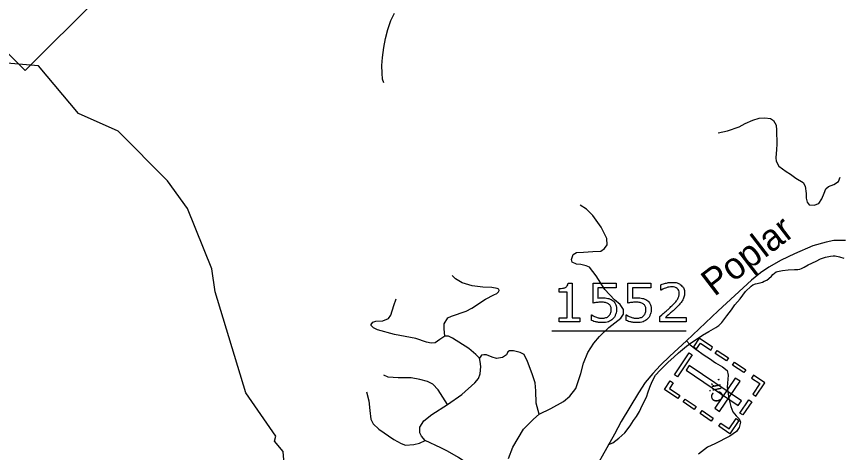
# Model space of a CAD drawing. Extents: x 1190067 to 1192950, y 891516 to 893460.
# Drawn here: x 1190959.3 to 1191052.1, y 893251.8 to 893300.9 of the extents above; entities that cross this region are included whole.
import ezdxf

# ---------------------------------------------------------------- set-up
doc = ezdxf.new("R2010")
doc.units = 0
doc.layers.add('Default', color=7, linetype='Continuous')

msp = doc.modelspace()

# ---------------------------------------------------------------- linework, layer by layer
at = {"layer": 'Default'}
for p, q in [((1190960.312, 893294.828), (1190948.657, 893306.483)), ((1190971.967, 893306.483), (1190960.312, 893294.828)), ((1191019.654, 893265.501), (1191034.784, 893265.501))]:
    msp.add_line(p, q, dxfattribs=at)
for points in [[(1190980.698, 893248.449), (1190979.491, 893247.036), (1190979.736, 893245.425), (1190981.503, 893246.077), (1190983.883, 893247.925), (1190988.976, 893247.078), (1190989.711, 893247.637), (1190989.396, 893251.894), (1190988.398, 893253.063), (1190988.573, 893253.634), (1190985.196, 893258.527), (1190981.713, 893269.914), (1190981.344, 893272.506), (1190978.598, 893279.282), (1190976.358, 893282.428), (1190970.811, 893287.999), (1190966.348, 893289.983), (1190961.814, 893295.359), (1190956.881, 893295.802), (1190952.522, 893297.095), (1190945.977, 893297.974), (1190942.094, 893299.83), (1190938.664, 893302.599), (1190934.899, 893303.824)], [(1190980.698, 893248.449), (1190979.491, 893247.036), (1190979.736, 893245.425), (1190981.503, 893246.077), (1190983.883, 893247.925), (1190988.976, 893247.078), (1190989.711, 893247.637), (1190989.396, 893251.894), (1190988.398, 893253.063), (1190988.573, 893253.634), (1190985.196, 893258.527), (1190981.713, 893269.914), (1190981.344, 893272.506), (1190978.598, 893279.282), (1190976.358, 893282.428), (1190970.811, 893287.999), (1190966.348, 893289.983), (1190961.814, 893295.359), (1190956.881, 893295.802), (1190952.522, 893297.095), (1190945.977, 893297.974), (1190942.094, 893299.83), (1190938.664, 893302.599), (1190934.899, 893303.824)], [(1191000.721, 893293.475), (1191000.59, 893293.864), (1191000.54, 893294.532), (1191000.491, 893295.407), (1191000.588, 893296.317), (1191000.725, 893297.433), (1191000.926, 893298.441), (1191001.198, 893299.45), (1191001.507, 893300.492), (1191001.914, 893301.321)], [(1191038.388, 893287.808), (1191039.447, 893288.049), (1191040.769, 893288.482), (1191041.419, 893288.891), (1191042.285, 893289.252), (1191043.006, 893289.469), (1191043.655, 893289.493), (1191044.281, 893289.445), (1191044.618, 893289.204), (1191044.93, 893288.699), (1191044.978, 893288.121), (1191045.002, 893286.532), (1191044.978, 893285.931), (1191044.882, 893284.992), (1191044.93, 893284.631), (1191045.243, 893284.054), (1191046.061, 893283.476), (1191046.542, 893283.163), (1191047.143, 893282.706), (1191047.985, 893282.224), (1191048.201, 893281.815), (1191048.297, 893280.997), (1191048.321, 893280.467), (1191048.418, 893280.01), (1191048.658, 893279.721), (1191049.211, 893279.673), (1191049.74, 893279.866), (1191050.053, 893280.371), (1191050.342, 893281.021), (1191050.51, 893281.502), (1191050.823, 893281.767), (1191051.424, 893281.984), (1191051.929, 893282.321), (1191052.145, 893282.826)], [(1191014.771, 893251.105), (1191015.276, 893252.381), (1191016.454, 893254.426), (1191017.585, 893255.534), (1191018.21, 893256.111), (1191019.557, 893256.761), (1191020.952, 893257.531), (1191021.673, 893258.133), (1191022.347, 893258.999), (1191022.924, 893260.708), (1191023.236, 893261.863), (1191023.693, 893263.043), (1191024.367, 893264.102), (1191025.04, 893264.872), (1191026.074, 893265.859), (1191027.445, 893266.942), (1191027.734, 893267.375), (1191027.734, 893267.904), (1191027.349, 893268.458), (1191026.724, 893269.011), (1191025.642, 893270.167), (1191024.631, 893271.683), (1191023.91, 893272.67), (1191023.525, 893272.814), (1191022.924, 893272.983), (1191022.419, 893273.007), (1191021.938, 893273.223), (1191021.866, 893273.56), (1191022.058, 893274.09), (1191022.419, 893274.33), (1191023.212, 893274.378), (1191024.271, 893274.427), (1191025.185, 893274.499), (1191025.593, 893274.764), (1191025.906, 893275.197), (1191025.858, 893275.919), (1191025.209, 893277.194), (1191024.283, 893278.518), (1191023.561, 893279.216), (1191022.84, 893279.649)], [(1191052.747, 893275.702), (1191051.436, 893275.702), (1191050.546, 893275.486), (1191049.055, 893275.076), (1191046.987, 893274.186), (1191045.471, 893273.464), (1191044.1, 893272.67), (1191043.163, 893272.044), (1191042.152, 893271.226), (1191038.4, 893267.76), (1191034.829, 893264.39), (1191032.941, 893262.658), (1191031.883, 893261.623), (1191031.017, 893260.708), (1191030.151, 893259.673), (1191029.43, 893258.518), (1191027.481, 893255.269), (1191026.712, 893253.849), (1191023.609, 893248.289), (1191022.623, 893246.484)], [(1191026.025, 893252.687), (1191026.52, 893252.885), (1191027.2, 893253.391), (1191027.884, 893254.004), (1191028.465, 893254.794), (1191028.865, 893255.377), (1191029.193, 893255.859), (1191029.524, 893256.41), (1191029.821, 893257.069), (1191030.082, 893257.587), (1191030.342, 893258.14), (1191030.455, 893258.522), (1191030.683, 893259.146), (1191030.945, 893259.771), (1191031.35, 893260.494), (1191031.856, 893261.075), (1191032.757, 893261.963), (1191033.403, 893262.541), (1191033.939, 893263.017), (1191034.836, 893263.763), (1191035.514, 893264.269), (1191036.013, 893264.606), (1191036.621, 893265.01), (1191037.332, 893265.412), (1191038.116, 893265.878), (1191038.473, 893266.115), (1191038.796, 893266.456), (1191039.376, 893267.176), (1191039.885, 893267.863), (1191040.285, 893268.448), (1191040.865, 893269.097), (1191041.482, 893269.921), (1191042.096, 893270.534), (1191042.309, 893270.669), (1191042.591, 893270.802), (1191043.12, 893270.927), (1191043.403, 893270.99), (1191043.579, 893271.091), (1191043.865, 893271.221), (1191044.114, 893271.39), (1191044.401, 893271.663), (1191044.546, 893271.835), (1191044.726, 893272.004), (1191044.941, 893272.138), (1191045.081, 893272.205), (1191045.644, 893272.294), (1191046.278, 893272.382), (1191046.978, 893272.398), (1191047.365, 893272.424), (1191047.575, 893272.452), (1191047.787, 893272.517), (1191048.07, 893272.684), (1191048.535, 893272.953), (1191049.421, 893273.349), (1191049.916, 893273.615), (1191050.483, 893273.811), (1191051.049, 893273.934), (1191051.329, 893273.963), (1191051.573, 893273.956), (1191052.061, 893273.837), (1191052.547, 893273.685)], [(1191007.618, 893264.889), (1191007.512, 893265.717), (1191007.538, 893266.279), (1191007.939, 893266.974), (1191008.366, 893267.161), (1191009.995, 893267.722), (1191010.636, 893268.043), (1191012.185, 893269.058), (1191013.12, 893269.566), (1191013.467, 893269.726), (1191013.654, 893269.887), (1191013.734, 893270.047), (1191013.681, 893270.18), (1191013.494, 893270.287), (1191012.906, 893270.368), (1191011.891, 893270.421), (1191010.69, 893270.555), (1191009.541, 893270.929), (1191008.82, 893271.356), (1191008.42, 893271.757)], [(1191021.48, 893270.88), (1191021.933, 893270.88), (1191021.933, 893266.96), (1191022.821, 893266.96), (1191022.821, 893266.516)], [(1191024.293, 893268.625), (1191024.293, 893270.866), (1191026.91, 893270.866), (1191026.91, 893270.355), (1191024.854, 893270.355), (1191024.854, 893269.199)], [(1191028.198, 893268.625), (1191028.198, 893270.866), (1191030.815, 893270.866), (1191030.815, 893270.355), (1191028.759, 893270.355), (1191028.759, 893269.199)], [(1191022.821, 893266.516), (1191020.467, 893266.516), (1191020.467, 893266.96), (1191021.372, 893266.96), (1191021.372, 893269.875), (1191020.467, 893269.875), (1191020.467, 893270.273)], [(1191031.972, 893270.074), (1191031.943, 893270.074), (1191031.943, 893270.687)], [(1191007.618, 893264.889), (1191007.031, 893264.515), (1191006.523, 893264.167), (1191006.069, 893264.114), (1191005.535, 893264.221), (1191004.333, 893264.622), (1191001.93, 893265.103), (1191000.007, 893265.611), (1190999.566, 893265.824), (1190999.299, 893266.118), (1190999.299, 893266.225), (1190999.486, 893266.466), (1190999.834, 893266.573), (1191000.635, 893266.626), (1191001.249, 893266.893), (1191001.516, 893267.267), (1191001.863, 893268.363), (1191002.104, 893269.111)], [(1191024.105, 893266.678), (1191024.105, 893267.294), (1191024.146, 893267.294)], [(1191028.01, 893266.678), (1191028.01, 893267.294), (1191028.051, 893267.294)], [(1191034.784, 893266.516), (1191031.836, 893266.516), (1191031.836, 893267.131)], [(1191032.441, 893267.02), (1191034.784, 893267.02), (1191034.784, 893266.516)], [(1191007.899, 893257.192), (1191009.528, 893258.341), (1191010.97, 893259.624), (1191011.397, 893260.132), (1191011.584, 893260.64), (1191011.638, 893261.468), (1191011.571, 893262.056), (1191011.491, 893262.404), (1191011.09, 893262.831), (1191010.289, 893263.526), (1191008.473, 893264.675), (1191008.019, 893264.916), (1191007.618, 893264.889)], [(1191034.829, 893264.39), (1191035.238, 893263.933), (1191035.887, 893263.452), (1191036.825, 893262.754), (1191037.402, 893262.369), (1191038.076, 893261.887), (1191038.893, 893261.454), (1191039.399, 893261.021), (1191039.519, 893260.516), (1191039.423, 893259.168), (1191039.591, 893257.892), (1191039.831, 893256.978), (1191040.048, 893256.352), (1191040.433, 893255.919), (1191040.769, 893255.582), (1191040.914, 893255.197), (1191040.757, 893254.595), (1191040.469, 893254.162), (1191039.699, 893253.632), (1191038.016, 893252.766), (1191037.198, 893252.381), (1191036.188, 893251.611)], [(1191018.21, 893256.111), (1191017.887, 893257.353), (1191017.86, 893258.742), (1191017.78, 893259.624), (1191017.433, 893260.64), (1191016.925, 893262.029), (1191016.525, 893262.831), (1191016.098, 893263.072), (1191015.323, 893263.232), (1191014.896, 893263.259), (1191014.682, 893263.152), (1191014.549, 893262.804), (1191014.095, 893262.484), (1191013.427, 893262.377), (1191012.92, 893262.537), (1191012.279, 893262.778), (1191012.011, 893262.804), (1191011.718, 893262.751), (1191011.491, 893262.404)], [(1191007.899, 893257.192), (1191006.857, 893258.849), (1191006.243, 893259.491), (1191005.655, 893259.785), (1191004.801, 893260.025), (1191003.813, 893260.185), (1191002.344, 893260.212), (1191001.222, 893260.266), (1191000.742, 893260.506)], [(1190998.765, 893258.609), (1190999.032, 893257.593), (1190999.166, 893256.524), (1190999.273, 893255.535), (1190999.513, 893255.028), (1191000.181, 893254.413), (1191001.863, 893253.237), (1191002.664, 893252.783), (1191003.172, 893252.622), (1191004.106, 893252.676), (1191004.747, 893252.836), (1191005.375, 893253.157)], [(1191005.375, 893253.157), (1191004.961, 893253.638), (1191004.774, 893254.012), (1191004.774, 893254.627), (1191005.228, 893255.348), (1191006.136, 893256.07), (1191007.899, 893257.192)], [(1191012.319, 893248.293), (1191011.918, 893248.827), (1191010.743, 893250.03), (1191010.503, 893250.271), (1191009.968, 893250.671), (1191009.141, 893251.233), (1191007.885, 893251.927), (1191007.164, 893252.328), (1191005.375, 893253.157)]]:
    msp.add_lwpolyline(points, dxfattribs=at)
for points in [[(1191035.618, 893263.71), (1191035.95, 893263.484), (1191036.383, 893264.121), (1191037.553, 893263.325), (1191037.772, 893263.648), (1191036.27, 893264.669)], [(1191038.292, 893263.293), (1191039.546, 893262.44), (1191039.322, 893262.111), (1191038.068, 893262.963)], [(1191035.469, 893262.779), (1191033.799, 893260.324), (1191033.469, 893260.548), (1191035.139, 893263.004)], [(1191040.643, 893257.078), (1191041.011, 893257.619), (1191035.142, 893261.61), (1191034.774, 893261.069)], [(1191040.238, 893261.97), (1191041.491, 893261.117), (1191041.267, 893260.788), (1191040.014, 893261.64)], [(1191042.384, 893260.51), (1191042.16, 893260.181), (1191043.092, 893259.547), (1191042.293, 893258.374), (1191042.616, 893258.155), (1191043.637, 893259.657)], [(1191033.001, 893259.865), (1191033.334, 893259.639), (1191032.901, 893259.002), (1191034.07, 893258.207), (1191033.851, 893257.885), (1191032.349, 893258.906)], [(1191040.864, 893259.815), (1191040.324, 893260.183), (1191038.006, 893256.775), (1191038.547, 893256.407)], [(1191034.665, 893257.813), (1191035.918, 893256.961), (1191035.694, 893256.631), (1191034.441, 893257.484)], [(1191042.179, 893257.514), (1191041.159, 893256.014), (1191040.829, 893256.238), (1191041.849, 893257.738)], [(1191036.572, 893256.515), (1191037.826, 893255.662), (1191037.602, 893255.333), (1191036.348, 893256.185)], [(1191038.462, 893254.746), (1191038.686, 893255.075), (1191039.618, 893254.441), (1191040.415, 893255.615), (1191040.738, 893255.396), (1191039.716, 893253.894)]]:
    msp.add_lwpolyline(points, close=True, dxfattribs=at)
for points in [[(1191020.467, 893270.273), (1191020.651, 893270.273), (1191020.861, 893270.304), (1191021.071, 893270.334), (1191021.18, 893270.393), (1191021.314, 893270.466), (1191021.391, 893270.578), (1191021.469, 893270.69), (1191021.48, 893270.88)], [(1191031.943, 893270.687), (1191032.15, 893270.789), (1191032.497, 893270.874), (1191032.844, 893270.958), (1191033.168, 893270.958), (1191033.838, 893270.958), (1191034.219, 893270.636), (1191034.599, 893270.313), (1191034.599, 893269.761), (1191034.599, 893269.513), (1191034.536, 893269.299), (1191034.473, 893269.084), (1191034.35, 893268.892), (1191034.236, 893268.711), (1191034.083, 893268.535), (1191033.929, 893268.36), (1191033.71, 893268.147), (1191033.397, 893267.841), (1191033.064, 893267.553), (1191032.731, 893267.266), (1191032.441, 893267.02)], [(1191031.836, 893267.131), (1191032.144, 893267.394), (1191032.453, 893267.657), (1191032.762, 893267.92), (1191033.028, 893268.18), (1191033.59, 893268.723), (1191033.798, 893269.042), (1191034.006, 893269.362), (1191034.006, 893269.733), (1191034.006, 893270.072), (1191033.782, 893270.263), (1191033.558, 893270.454), (1191033.156, 893270.454), (1191032.889, 893270.454), (1191032.579, 893270.361), (1191032.268, 893270.267), (1191031.972, 893270.074)], [(1191024.854, 893269.199), (1191024.98, 893269.21), (1191025.112, 893269.216), (1191025.243, 893269.222), (1191025.34, 893269.222), (1191025.693, 893269.222), (1191025.959, 893269.162), (1191026.225, 893269.102), (1191026.448, 893268.95), (1191026.682, 893268.789), (1191026.81, 893268.535), (1191026.939, 893268.28), (1191026.939, 893267.897)], [(1191028.759, 893269.199), (1191028.885, 893269.21), (1191029.016, 893269.216), (1191029.148, 893269.222), (1191029.244, 893269.222), (1191029.598, 893269.222), (1191029.864, 893269.162), (1191030.13, 893269.102), (1191030.352, 893268.95), (1191030.586, 893268.789), (1191030.715, 893268.535), (1191030.843, 893268.28), (1191030.843, 893267.897)], [(1191024.146, 893267.294), (1191024.386, 893267.142), (1191024.707, 893267.035), (1191025.028, 893266.928), (1191025.338, 893266.928), (1191025.545, 893266.928), (1191025.74, 893266.987), (1191025.934, 893267.045), (1191026.086, 893267.192), (1191026.214, 893267.317), (1191026.28, 893267.493), (1191026.346, 893267.669), (1191026.346, 893267.9), (1191026.346, 893268.126), (1191026.268, 893268.281), (1191026.191, 893268.436), (1191026.054, 893268.53), (1191025.902, 893268.641), (1191025.684, 893268.686), (1191025.467, 893268.732), (1191025.198, 893268.732), (1191024.941, 893268.732), (1191024.704, 893268.696), (1191024.466, 893268.661), (1191024.293, 893268.625)], [(1191028.051, 893267.294), (1191028.29, 893267.142), (1191028.612, 893267.035), (1191028.933, 893266.928), (1191029.243, 893266.928), (1191029.45, 893266.928), (1191029.644, 893266.987), (1191029.838, 893267.045), (1191029.99, 893267.192), (1191030.119, 893267.317), (1191030.185, 893267.493), (1191030.25, 893267.669), (1191030.25, 893267.9), (1191030.25, 893268.126), (1191030.173, 893268.281), (1191030.096, 893268.436), (1191029.958, 893268.53), (1191029.807, 893268.641), (1191029.589, 893268.686), (1191029.372, 893268.732), (1191029.103, 893268.732), (1191028.846, 893268.732), (1191028.608, 893268.696), (1191028.37, 893268.661), (1191028.198, 893268.625)], [(1191026.939, 893267.897), (1191026.939, 893267.593), (1191026.828, 893267.316), (1191026.717, 893267.038), (1191026.524, 893266.848), (1191026.314, 893266.643), (1191026.023, 893266.533), (1191025.732, 893266.424), (1191025.35, 893266.424), (1191024.993, 893266.424), (1191024.663, 893266.498), (1191024.333, 893266.573), (1191024.105, 893266.678)], [(1191030.843, 893267.897), (1191030.843, 893267.593), (1191030.732, 893267.316), (1191030.621, 893267.038), (1191030.429, 893266.848), (1191030.218, 893266.643), (1191029.928, 893266.533), (1191029.637, 893266.424), (1191029.254, 893266.424), (1191028.898, 893266.424), (1191028.568, 893266.498), (1191028.238, 893266.573), (1191028.01, 893266.678)]]:
    msp.add_open_spline(points, degree=3, dxfattribs=at)

# ---------------------------------------------------------------- texts
for s, height, rotation, p in [('Poplar', 3, 37.46295, (1191037.961, 893269.303)), ('Cir.', 1.3125, 101.42481, (1191039.037, 893257.591))]:
    msp.add_text(s, height=height, rotation=rotation, dxfattribs=at).set_placement(p)

doc.saveas('drawing.dxf')
